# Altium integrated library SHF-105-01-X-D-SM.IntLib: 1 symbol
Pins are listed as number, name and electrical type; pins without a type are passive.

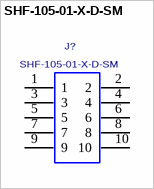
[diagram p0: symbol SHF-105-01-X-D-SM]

## SHF-105-01-X-D-SM
designator J?
0.05"X0.05" SHROUDED TERMINAL STRIP, 10 PINS.; MANUFACTURER: SAMTEC
footprint SHF-105-01-X-D-SM
pins: 1, 2, 3, 4, 5, 6, 7, 8, 9, 10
